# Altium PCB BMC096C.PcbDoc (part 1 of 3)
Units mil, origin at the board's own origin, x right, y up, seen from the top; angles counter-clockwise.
Board outline 5500 x 3200 mil, 4 copper layers (Top Layer, Signal Layer 1, Signal Layer 2, Bottom Layer), stack 61.6 mil thick; 174 components, 74 nets, 402 pads, 1110 vias.
Unrouted connection lines stored in the file: 741.
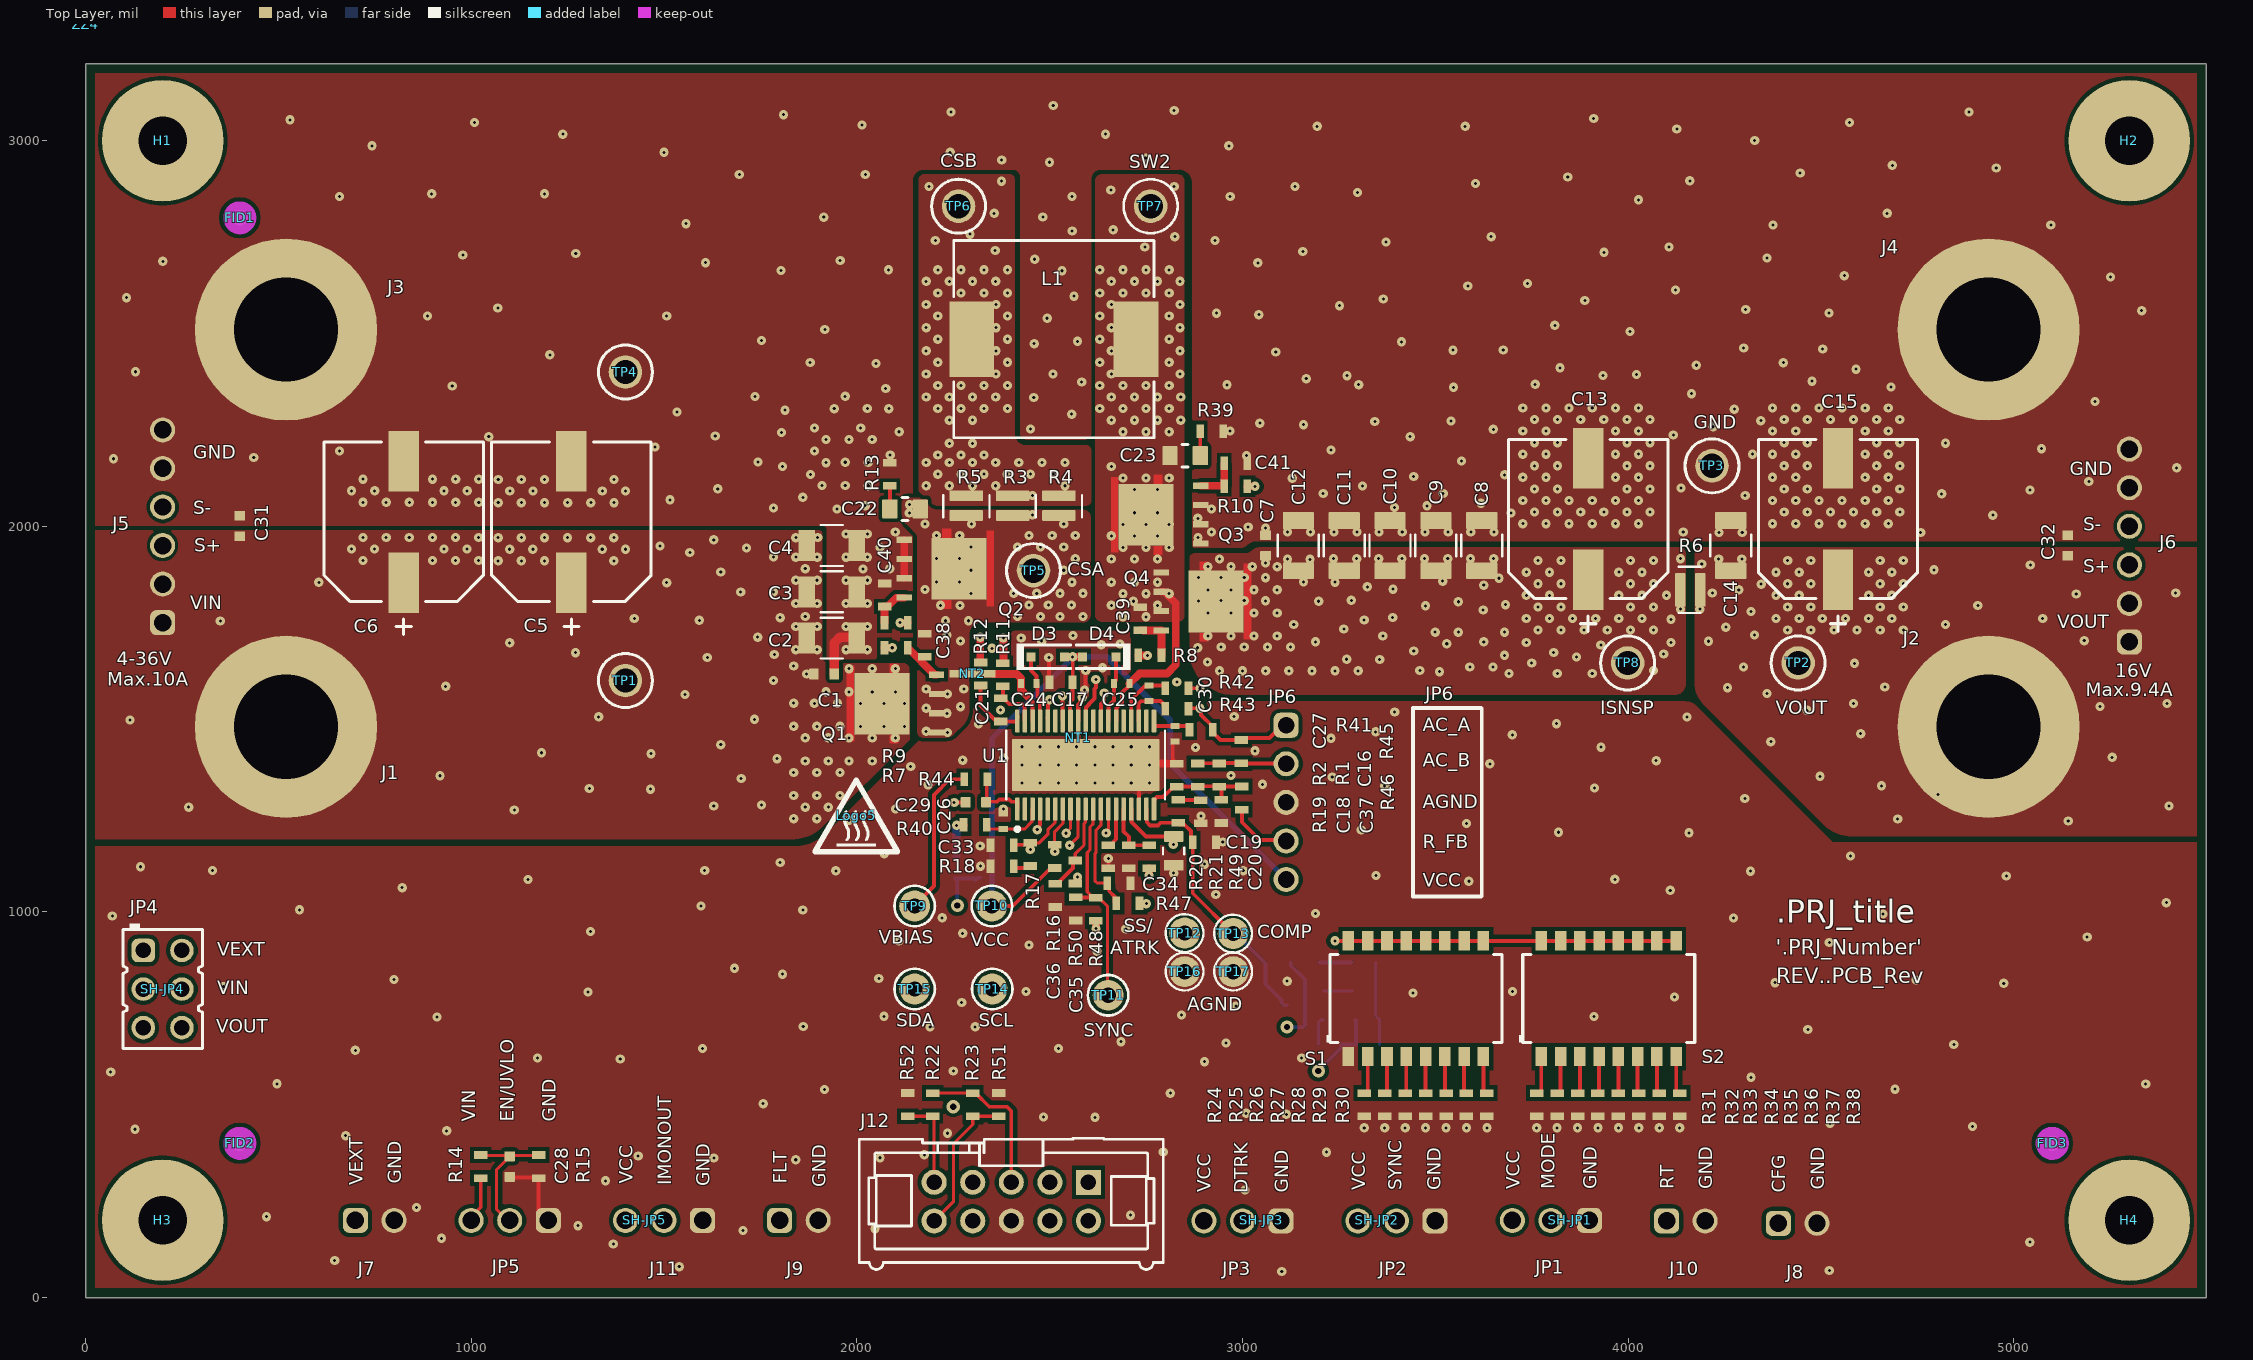
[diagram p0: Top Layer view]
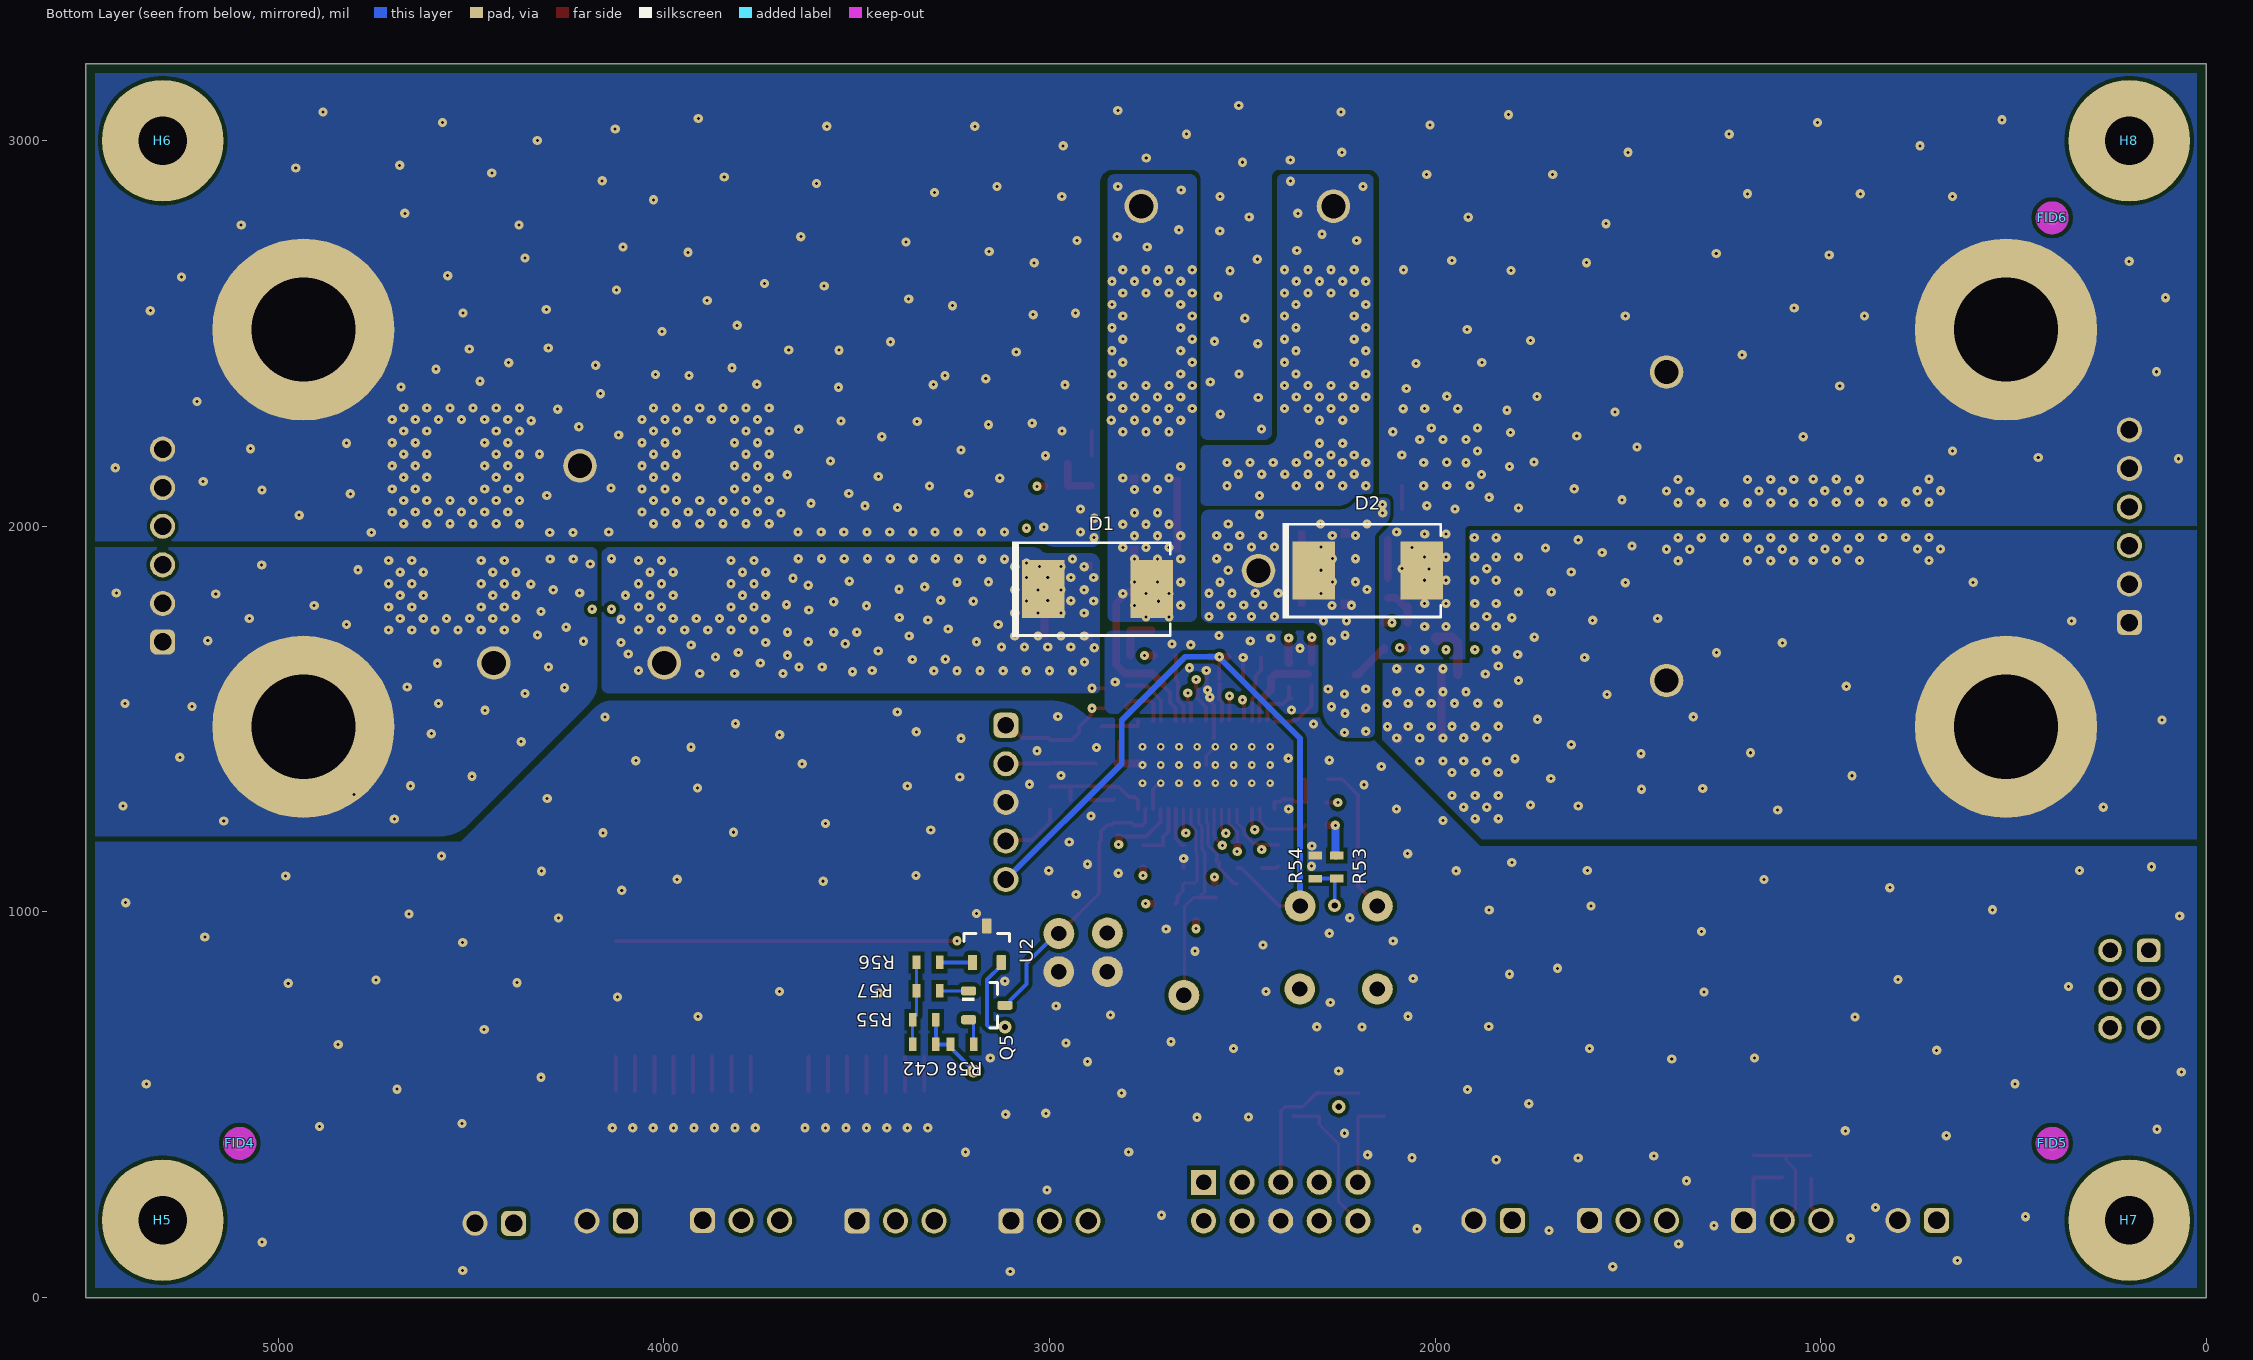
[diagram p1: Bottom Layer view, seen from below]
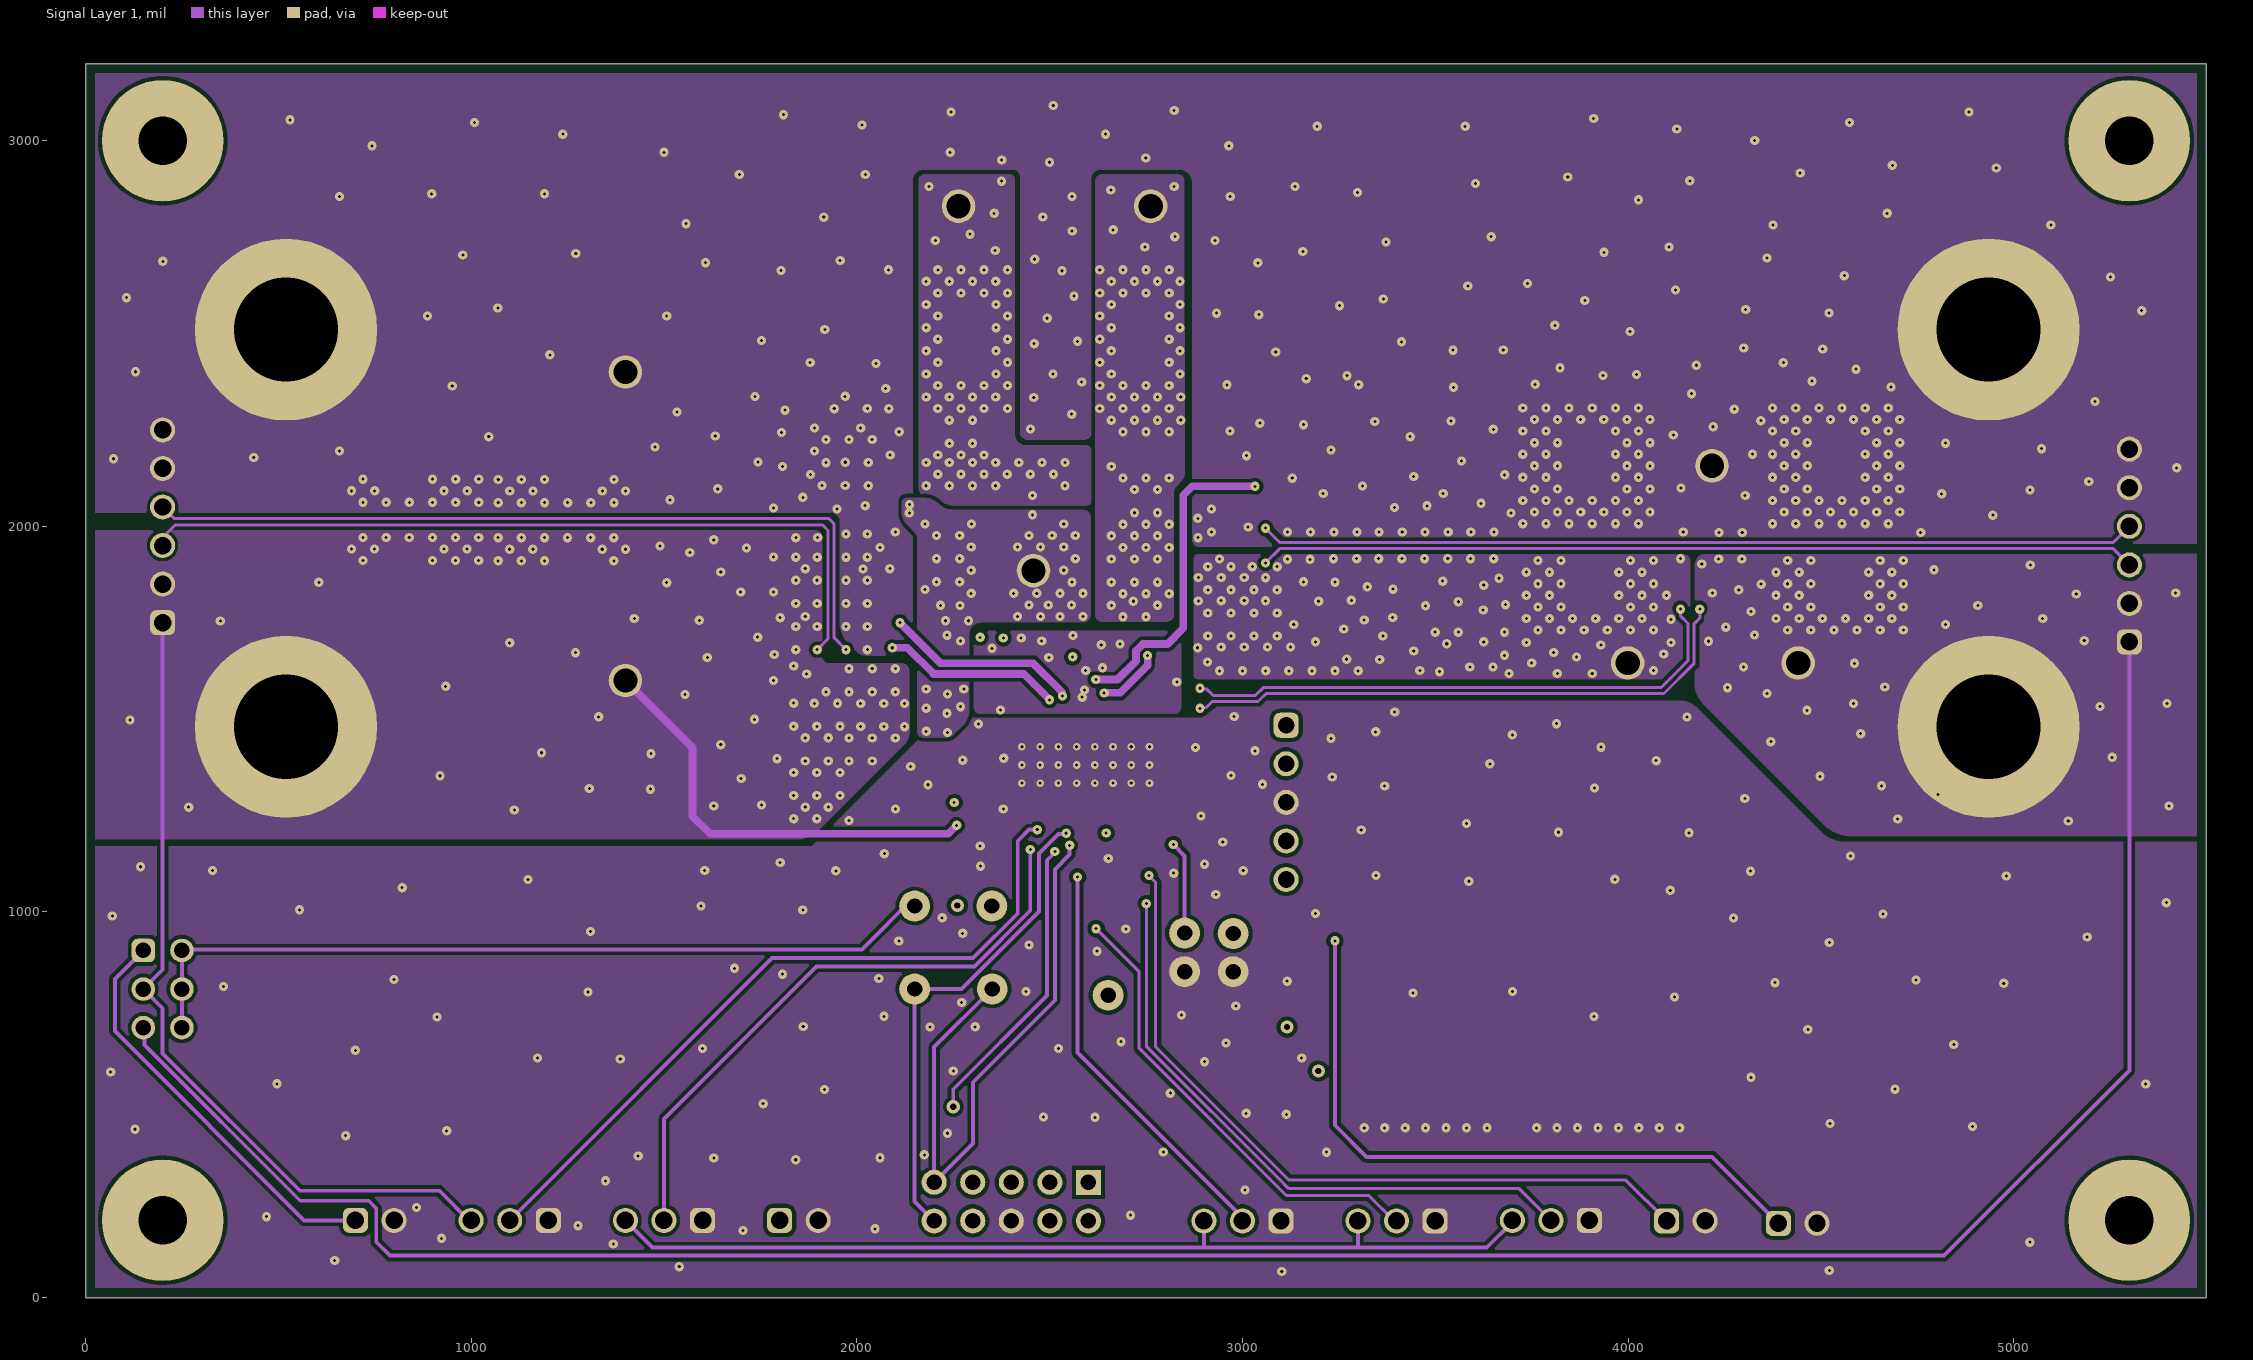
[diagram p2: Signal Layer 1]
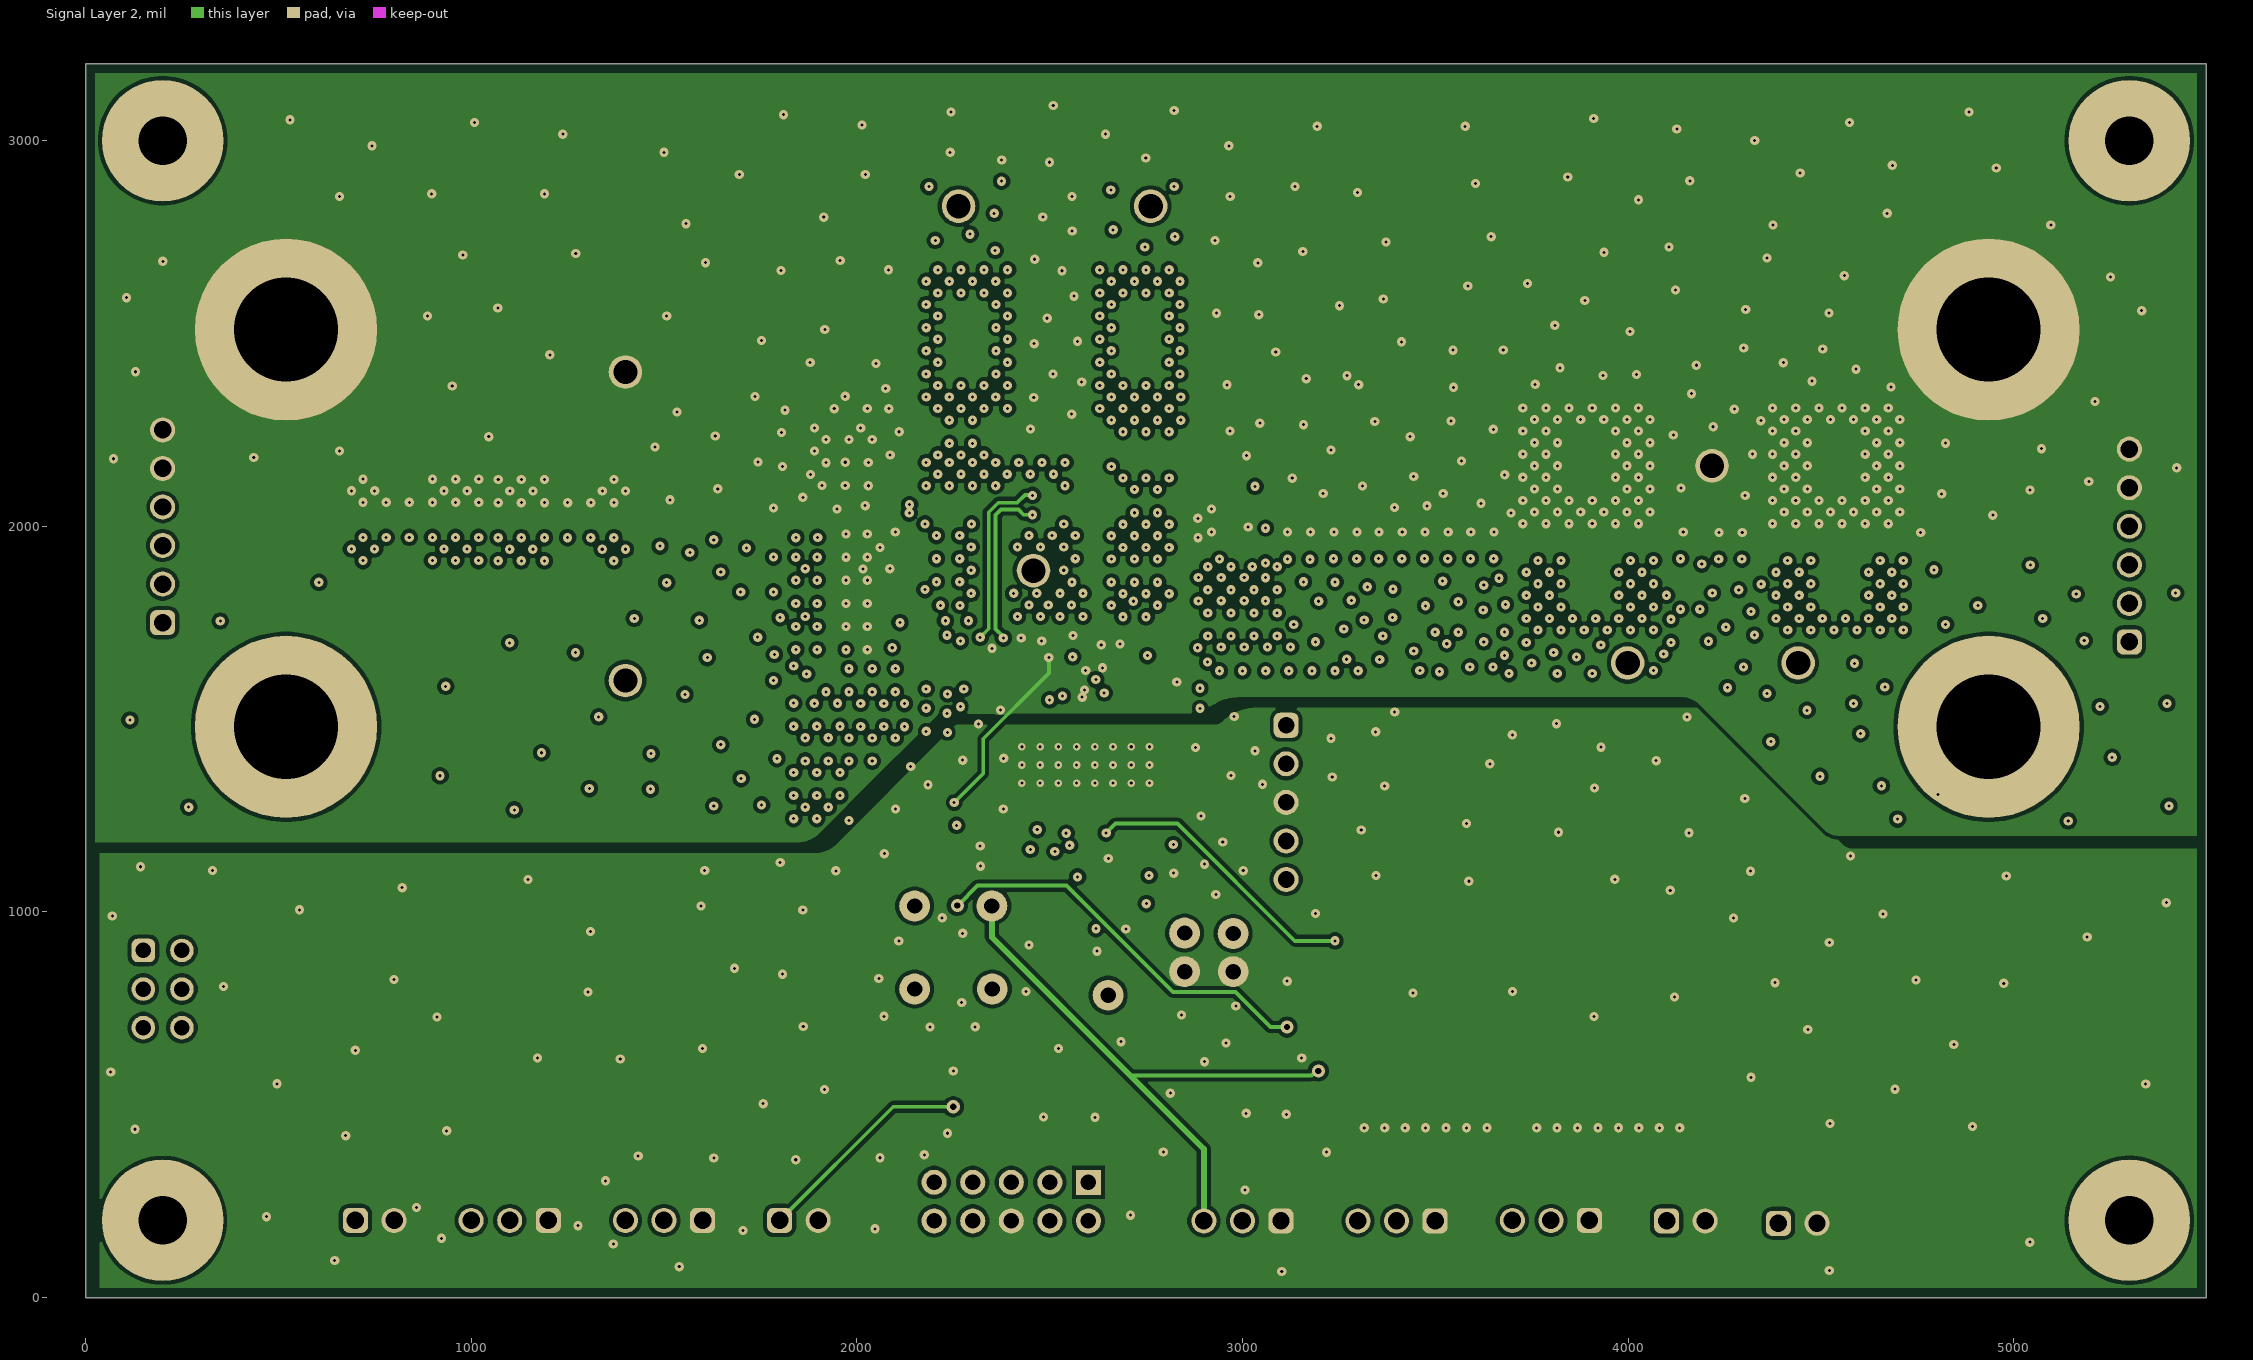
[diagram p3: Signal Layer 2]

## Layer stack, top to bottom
Top Solder: solder mask 0.4, Solder Resist, Dk 3.5
Top Layer: signal copper 2.8
Dielectric 1: prepreg 8, FR-4 High Tg, Dk 4.2
Signal Layer 1: signal copper 1.4
Dielectric 2: core 37.2, FR-4 High Tg, Dk 4.2
Signal Layer 2: signal copper 1.4
Dielectric 3: prepreg 8, FR-4 High Tg, Dk 4.2
Bottom Layer: signal copper 2.8
Bottom Solder: solder mask 0.4, Solder Resist, Dk 3.5

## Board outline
0,0 0,3200 5500,3200 5500,0

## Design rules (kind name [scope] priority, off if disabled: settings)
AcuteAngle [All] p1: minimum=4.50000000000000E+0001 checktracksonly=TRUE
AssemblyTestPointUsage [All] p1: valid=2
BoardOutlineClearance BoardOutlineClearance_MountingHoles [OnCopper and InComponentClass('Mounting Holes')] p1: gap=39.37 ignorepadtopadclearanceinfootprint=FALSE
BoardOutlineClearance BoardOutlineClearance_Poly [OnCopper and IsPoly] p2: gap=25 ignorepadtopadclearanceinfootprint=FALSE
BoardOutlineClearance [OnCopper and Not InComponentClass('Logo') and not InComponentClass('FiducialMark') and not InRegion(1000,500,4000,800) and not InPoly] p3: gap=40 ignorepadtopadclearanceinfootprint=FALSE
Clearance Clearance_Keepouts [((IsTrack Or IsArc) And Not InPoly) And IsFree and IsKeepOut vs ((IsTrack Or IsArc) And Not InPoly) And IsFree and IsKeepOut] p1: gap=0 ignorepadtopadclearanceinfootprint=FALSE
Clearance Clearance_Poly [InPolygon] p2: gap=10 ignorepadtopadclearanceinfootprint=TRUE
Clearance Clearance_FiducialMark [IsKeepOut and InComponentClass('FiducialMark') vs IsPad and InComponentClass('FiducialMark')] p3: gap=0 ignorepadtopadclearanceinfootprint=FALSE
Clearance [All] p4: gap=7.87 ignorepadtopadclearanceinfootprint=TRUE
ComponentClearance ComponentClearance_L1_TP [InComponent('L1')] p1: gap=25 collisioncheckmode=3 verticalgap=10 showdistances=FALSE
ComponentClearance ComponentClearance_TP [InComponent('TP15')or InComponent('TP16')or InComponent('TP17')or InComponent('TP18')or InComponent('TP23')or InComponent('TP24')or InComponent('TP12')or InComponent('TP13')or InComponent('TP21')or InComponent('TP22')] p2: gap=0 collisioncheckmode=3 verticalgap=0 showdistances=FALSE
ComponentClearance ComponentClearance_NT1 [InComponent('NT1') or InComponent('NT2')] p3: gap=0 collisioncheckmode=3 verticalgap=0 showdistances=FALSE
ComponentClearance ComponentClearance_MountingHoles_FiducialMarks [InComponentClass('Mounting Holes') vs InComponentClass('FiducialMark')] p4: gap=50 collisioncheckmode=3 verticalgap=10 showdistances=FALSE
ComponentClearance ComponentClearance_Shunt [InComponentClass('Header') vs InComponent('SH-JP1') or InComponent('SH-JP2') or InComponent('SH-JP3') or InComponent('SH-JP4') or InComponent('SH-JP5')] p5: gap=0 collisioncheckmode=3 verticalgap=0 showdistances=FALSE
ComponentClearance ComponentClearance_Logo [InComponentClass('Logo')] p6: gap=30 collisioncheckmode=3 verticalgap=10 showdistances=FALSE
ComponentClearance ComponentClearance_ScrewToNut [(HasFootprint('NY PMS 440 0025 PH')) vs (HasFootprint('Keystone_1902C'))] p7: gap=5 collisioncheckmode=3 verticalgap=10 showdistances=FALSE
ComponentClearance ComponentClearance_MountingHoles [InComponentClass('Mounting Holes')] p8: gap=100 collisioncheckmode=3 verticalgap=100000 showdistances=FALSE
ComponentClearance ComponentClearance_SmallPassives [HasFootprint('0201*') or HasFootprint('0402*') or HasFootprint('0508') or HasFootprint('0603*') or HasFootprint('0612') or HasFootprint('0805*') or HasFootprint('0815*') or HasFootprint('0830*') or HasFootprint('1206*') or HasFootprint('1210*') or HasFootprint('1808*') or HasFootprint('1812*') or HasFootprint('1825*') or HasFootprint('2010*') or HasFootprint('2220*') or HasFootprint('2225*') or HasFootprint('2512*') or HasFootprint('2728*') or HasFootprint('3518*') vs HasFootprint('0201*') or HasFootprint('0402*') or HasFootprint('0508') or HasFootprint('0603*') or HasFootprint('0612') or HasFootprint('0805*') or HasFootprint('0815*') or HasFootprint('0830*') or HasFootprint('1206*') or HasFootprint('1210*') or HasFootprint('1808*') or HasFootprint('1812*') or HasFootprint('1825*') or HasFootprint('2010*') or HasFootprint('2220*') or HasFootprint('2225*') or HasFootprint('2512*') or HasFootprint('2728*') or HasFootprint('3518*')] p9: gap=14.96 collisioncheckmode=3 verticalgap=10 showdistances=FALSE
ComponentClearance ComponentClearance_THtoSMT [IsThruComponent vs IsSMTComponent] p10: gap=30 collisioncheckmode=3 verticalgap=30 showdistances=FALSE
ComponentClearance ComponentClearance_THtoTH [IsThruComponent vs IsThruComponent] p11: gap=20 collisioncheckmode=3 verticalgap=30 showdistances=FALSE
ComponentClearance [All] p12: gap=20 collisioncheckmode=3 verticalgap=10 showdistances=FALSE
DiffPairsRouting [All] p1: maxlimit=100 minlimit=10 mostfreqgap=10 toplayer_minwidth=15 toplayer_maxwidth=15 toplayer_prefwidth=15 midlayer1_minwidth=15 midlayer1_maxwidth=15 midlayer1_prefwidth=15 midlayer2_minwidth=15 midlayer2_maxwidth=15 midlayer2_prefwidth=15 bottomlayer_minwidth=15 bottomlayer_maxwidth=15 bottomlayer_prefwidth=15 maxuncoupledlength=1000
FabricationTestPointUsage TestPointUsage [All] p1: valid=2 allowmultiple=FALSE
FabricationTestpoint Testpoint [All] p1: side=3 testpointundercomponent=TRUE minsize=40 maxsize=100 preferedsize=60 minholesize=0 maxholesize=40 preferedholesize=32 testpointgrid=1 allowsidetop=TRUE allowsidebottom=TRUE usegrid=TRUE gridtolerance=0.01
FanoutControl Fanout_LCC [IsLCC] p1: bgadir=Out bgaviamode=Centered fanoutstyle=Auto fanoutdirection=Alternating viagrid=1 // Fanout_LCC (Default Rule)
FanoutControl Fanout_BGA [IsBGA] p2: bgadir=Out bgaviamode=Centered fanoutstyle=Auto fanoutdirection=Alternating viagrid=1 // Fanout_BGA (Default Rule)
FanoutControl Fanout_Default [All] p4: bgadir=Out bgaviamode=Centered fanoutstyle=Auto fanoutdirection=Alternating viagrid=1 // Fanout_Default (Default Rule)
FanoutControl Fanout_Small [(CompPinCount < 5)] p5: bgadir=Out bgaviamode=Centered fanoutstyle=Auto fanoutdirection=OutThenIn viagrid=1 // Fanout_Small (Default Rule)
HoleSize [All] p1: absolutevalues=TRUE maxlimit=275 minlimit=7.87 maxpercent=80.000 minpercent=20.000
MinimumAnnularRing MinimumAnnularRing_ThermalPadVias [IsVia and InAnyComponent] p1: minimumring=5.91
MinimumAnnularRing [All] p2: minimumring=7.87
MinimumSolderMaskSliver MinimumSolderMaskSliver_Logo [InComponentClass('Logo') vs InComponentClass('Logo')] p1: minsoldermaskwidth=0.7
MinimumSolderMaskSliver [All] p2: minsoldermaskwidth=3.94
PlaneConnect [All] p1: planeconnectstyle=Relief reliefexpansion=10 reliefentries=4 reliefconductorwidth=10 reliefairgap=10
PolygonConnect [All] p1: connectstyle=Direct reliefconductorwidth=10 reliefentries=4 polygonreliefangle="90 Angle" airgapwidth=10
RoutingVias ThermalPadVias [IsVia and InAnyComponent] p1: holewidth=7.87 width=19.68 viastyle="Through Hole" minholewidth=7.87 minwidth=19.68 maxholewidth=12.99 maxwidth=23.62
RoutingVias [All] p2: holewidth=16 width=34 viastyle="Through Hole" minholewidth=7.87 minwidth=24 maxholewidth=40 maxwidth=65
SilkToBoardRegionClearance [Not ((IsComment or IsDesignator) And (Hide <> 'False')) and not InRegion(1000,500,4000,800)] p1:
SilkToSilkClearance SilkToSilkClearance_Pb-FreeLogo [(HasFootprint('Pb-Free_Overlay_Medium') OR HasFootprint('Pb-Free_Overlay_Small')) vs (HasFootprint('Pb-Free_Overlay_Medium') OR HasFootprint('Pb-Free_Overlay_Small'))] p1: silktosilkclearance=0
SilkToSilkClearance [All] p2: silktosilkclearance=3.94
SilkToSolderMaskClearance SilkToComponentPadClearance [(IsPad or IsFill or IsRegion) and InAnycomponent] p1: minsilkscreentomaskgap=5 clearancetoexposedcopper=TRUE
SilkToSolderMaskClearance "Silk to Solder Mask Opening" [All] p2: minsilkscreentomaskgap=3.94 clearancetoexposedcopper=FALSE
SolderMaskExpansion [All] p1: expansion=1.97 istentingtop=FALSE
UnRoutedNet [All] p1: checkbadconnections=TRUE
Width [All] p1: maxlimit=100 minlimit=6 preferedwidth=10
14 further rules are at their usual default settings.

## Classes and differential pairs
component class Header: J5 J6 J7 J8 J9 J10 J11 JP1 JP2 JP3 JP4 JP5 JP6
component class BMC096C: C1 C2 C3 C4 C5 C6 C7 C8 C9 C10 C11 C12 C13 C14 C15 C16 C17 C18 C19 C20 C21 C22 C23 C24 C25 C26 C27 C28 C29 C30 C31 C32 C33 C34 C35 C36 C37 C38 C39 C40 C41 C42 D1 D2 D3 D4 J1 J2 J3 J4 J5 J6 J7 J8 J9 J10 J11 J12 JP1 JP2 JP3 JP4 JP5 JP6 L1 NT1 NT2 Q1 Q2 Q3 Q4 Q5 R1 R2 R3 R4 R5 R6 R7 R8 R9 R10 R11 R12 R13 R14 R15 R16 R17 R18 R19 R20 R21 R22 R23 R24 R25 R26 R27 R28 R29 R30 R31 R32 R33 R34 R35 R36 R37 R38 R39 R40 R41 R42 R43 R44 R45 R46 R47 R48 R49 R50 R51 R52 R53 R54 R55 R56 R57 R58 S1 S2 TP1 TP2 TP3 TP4 TP5 TP6 TP7 TP8 TP9 TP10 TP11 TP12 TP13 TP14 TP15 TP16 TP17 U1 U2
component class "Mounting Holes": H1 H2 H3 H4
component class BMC096C_Hardware: FID1 FID2 FID3 FID4 FID5 FID6 H1 H2 H3 H4 H5 H6 H7 H8 Logo5 SH-JP1 SH-JP2 SH-JP3 SH-JP4 SH-JP5 ZZ2 ZZ3 ZZ4
component class FiducialMark: FID1 FID2 FID3 FID4 FID5 FID6
component class AssemblyNote: ZZ2 ZZ3 ZZ4

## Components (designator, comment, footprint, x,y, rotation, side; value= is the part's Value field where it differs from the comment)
C1 "GCM188L81H104KA57D" FP-GCM188L81H104KA57D_0603-MFG 1915,1616.93 r0 top
C2 "GCM32EC71H106KA03L" FP-GCM32EC71H106KA03L_1210-MFG 1935,1710 r180 top value=10µF
C3 "GCM32EC71H106KA03L" FP-GCM32EC71H106KA03L_1210-MFG 1935,1830 r180 top value=10µF
C4 "GCM32EC71H106KA03L" FP-GCM32EC71H106KA03L_1210-MFG 1935,1950 r180 top value=10µF
C5 "PCR1J101MCL1GS" CR_1000x1270 1260,2011.27 r90 top value=100uF
C6 "PCR1J101MCL1GS" CR_1000x1270 825,2011.27 r90 top value=100uF
C7 "GCM188L81H104KA57D" FP-GCM188L81H104KA57D_0603-MFG 3060,1950 r90 top
C8 "GCM32EC71H106KA03L" FP-GCM32EC71H106KA03L_1210-MFG 3620.57,1950 r270 top value=10µF
C9 "GCM32EC71H106KA03L" FP-GCM32EC71H106KA03L_1210-MFG 3501.57,1950 r270 top value=10µF
C10 "GCM32EC71H106KA03L" FP-GCM32EC71H106KA03L_1210-MFG 3382.57,1950 r270 top value=10µF
C11 "GCM32EC71H106KA03L" FP-GCM32EC71H106KA03L_1210-MFG 3264,1950 r270 top value=10µF
C12 "GCM32EC71H106KA03L" FP-GCM32EC71H106KA03L_1210-MFG 3145,1950 r270 top value=10µF
C13 "PCR1J101MCL1GS" CR_1000x1270 3896.71,2018.9 r90 top value=100uF
C14 "GCM32EC71H106KA03L" FP-GCM32EC71H106KA03L_1210-MFG 4266.29,1950 r270 top value=10µF
C15 "PCR1J101MCL1GS" CR_1000x1270 4544.43,2018.9 r90 top value=100uF
C16 "GRM1885C2A200JA01D" 0603S 2940.36,1354.65 r270 top value=20pF
C17 "GRM188R60J476ME15D" 0603S 2529.57,1596.16 r0 top value=47uF
C18 "CGA3E3X7R1H224K080AB" 0603S 2892.5,1259.7 r270 top value=0.22uF
C19 "06031C222JAT2A" 0603S 2901.25,1181.04 r0 top value=2200pF
C20 "GCM21B5C1H183JA16L" FP-GCM21B5C1H183JA16L_0805-MFG 2821.83,1158.17 r90 top value=18nF
C21 "GCM1885C1H101JA16J" 0603S 2373,1523.84 r90 top value=100pF
C22 "GRM2165C1H681JA01D" 0805_HV1 2125.06,2045.08 r0 top value=680pF
C23 "GRM2165C1H681JA01D" 0805_HV1 2851.36,2183 r180 top value=680pF
C24 "0402BB104KW500" 0402S 2445.98,1592 r0 top value=0.1uF
C25 "0402BB104KW500" 0402S 2687.04,1592 r180 top value=0.1uF
C26 "0402BB104KW500" 0402S 2380,1235 r270 top value=0.1uF
C27 "0402BB104KW500" 0402S 2824.91,1461.75 r270 top value=0.1uF
C28 "GCM188L81H104KA57D" FP-GCM188L81H104KA57D_0603-MFG 1100,339.5 r270 top
C29 "GCM188L81H104KA57D" FP-GCM188L81H104KA57D_0603-MFG 2308.95,1284.59 r0 top
C30 "0402BB104KW500" 0402S 2758,1567 r90 top value=0.1uF
C31 "GCM188L81H104KA57D" FP-GCM188L81H104KA57D_0603-MFG 400,2000.81 r90 top
C32 "GCM188L81H104KA57D" FP-GCM188L81H104KA57D_0603-MFG 5140,1950 r90 top
C33 "06031C222JAT2A" 0603S 2376.93,1173 r0 top value=2200pF
C34 "06031C102JAT2A" 0603S 2679.54,1074.91 r0 top value=1000pF
C35 "06031C102JAT2A" 0603S 2567.43,1007.87 r270 top value=1000pF
C36 "06031C102JAT2A" 0603S 2514.08,1042.87 r270 top value=1000pF
C37 "GRM1885C1H151JA01D" 0603S 2945.63,1260.58 r270 top value=150pF
C38 "GRM188R72A103KA01D" 0603S 2176.39,1691.59 r90 top value=0.01uF
C39 "GRM188R72A103KA01D" 0603S 2735.67,1760.07 r270 top value=0.01uF
C40 "GRM188R72A103KA01D" 0603S 2072,1821.71 r270 top value=0.01uF
C41 "GRM188R72A103KA01D" 0603S 2982.82,2163.32 r180 top value=0.01uF
C42 "C0603C183K1RACTU" 0603S 3325,656.26 r0 bottom value=0.018uF
D1 "B560C-13-F" SMC 2875.84,1836.98 r180 bottom value=60V
D2 "B560C-13-F" SMC 2175,1884.92 r180 bottom value=60V
D3 "PMEG6010CEJ,115" SOD-323F 2495,1661.5 r0 top value=60V
D4 "PMEG6010CEJ,115" SOD-323F 2629,1661.5 r180 top value=60V
FID1 "Fiducial" Fiducial10-20 400,2800 r0 top
FID2 "Fiducial" Fiducial10-20 400,400 r0 top
FID3 "Fiducial" Fiducial10-20 5100,400 r0 top
FID4 "Fiducial" Fiducial10-20 5100,400 r180 bottom
FID5 "Fiducial" Fiducial10-20 400,400 r180 bottom
FID6 "Fiducial" Fiducial10-20 400,2800 r180 bottom
H1 "NY PMS 440 0025 PH" "NY PMS 440 0025 PH" 200,3000 r0 top
H2 "NY PMS 440 0025 PH" "NY PMS 440 0025 PH" 5300,3000 r0 top
H3 "NY PMS 440 0025 PH" "NY PMS 440 0025 PH" 200,200 r0 top locked
H4 "NY PMS 440 0025 PH" "NY PMS 440 0025 PH" 5300,200 r0 top
H5 "1902C" Keystone_1902C 5300,200 r180 bottom locked
H6 "1902C" Keystone_1902C 5300,3000 r180 bottom
H7 "1902C" Keystone_1902C 200,200 r180 bottom locked
H8 "1902C" Keystone_1902C 200,3000 r180 bottom locked
J1 "108-0740-001" Johnson_108-0740-001 520,1480 r0 top
J2 "108-0740-001" Johnson_108-0740-001 4935,1480 r0 top
J3 "108-0740-001" Johnson_108-0740-001 520,2510 r0 top
J4 "108-0740-001" Johnson_108-0740-001 4935,2510 r0 top
J5 "61300611121" WURTH_61300611121 200,2000 r90 top
J6 "61300611121" WURTH_61300611121 5300,1950 r90 top
J7 "61300211121" WURTH_61300211121 750,200 r0 top
J8 "61300211121" WURTH_61300211121 4440,192.46 r0 top
J9 "61300211121" WURTH_61300211121 1850,200 r0 top
J10 "61300211121" WURTH_61300211121 4150,198.77 r0 top
J11 "61300311121" WURTH_61300311121 1500,200 r180 top
J12 "N2510-6002-RB" CONN_2510-6002 2400.67,248.77 r180 top
JP1 "61300311121" WURTH_61300311121 3800,200 r180 top
JP2 "61300311121" WURTH_61300311121 3399.6,198.77 r180 top
JP3 "61300311121" WURTH_61300311121 3000.04,198.77 r180 top
JP4 "HTSW-103-07-G-D" Samtec_HTSW-103-07-x-D 200,800 r0 top
JP5 "61300311121" WURTH_61300311121 1100,200 r180 top
JP6 "61300511121" Wurth_61300511121 3113.44,1284.08 r270 top
L1 "IHLP5050FDER1R8M01" IHLP-5050FD 2511.06,2485.11 r0 top value=1.8uH
Logo5 "CAUTION HOT SURFACE" IEC_HotSurface_Small 1998.65,1249.35 r0 top
NT1 "Net-Tie" Net-Tie_10mil 2574,1452 r270 top net-tie
NT2 "Net-Tie" Net-Tie_20milWide_60milLong 2299.97,1617.37 r180 top net-tie
Q1 "SQJ422EP-T1-GE3" PowerPAK_SO-8L 2096.69,1540 r180 top value=40V
Q2 "SQJ422EP-T1-GE3" PowerPAK_SO-8L 2233.31,1890 r0 top value=40V
Q3 "SQJ422EP-T1-GE3" PowerPAK_SO-8L 2781.69,2030 r180 top value=40V
Q4 "SQJ422EP-T1-GE3" PowerPAK_SO-8L 2900,1805 r0 top value=40V
Q5 "BC807-40LT1G" SOT-23 3162.89,757.78 r180 bottom value="45 V"
R1 "RC0603FR-0771K5L" 0603S 2883.75,1354.65 r270 top value=71.5k
R2 "RC0603FR-074K7L" 0603S 2830.06,1354.2 r270 top value=4.70k
R3 "KRL2012E-M-R004-F-T5" FP-KRL2012E-M-R004-F-T5_2012-MFG 2404.24,2053.56 r90 top value=4m
R4 "KRL2012E-M-R004-F-T5" FP-KRL2012E-M-R004-F-T5_2012-MFG 2524.24,2053.56 r90 top value=4m
R5 "KRL2012E-M-R004-F-T5" FP-KRL2012E-M-R004-F-T5_2012-MFG 2284.24,2053.56 r90 top value=4m
R6 "KRL2012E-M-R004-F-T5" FP-KRL2012E-M-R004-F-T5_2012-MFG 4161.29,1835 r0 top value=4m
R7 "CRCW06033R00JNEA" 0603S 2102,1685 r0 top value=3.0
R8 "CRCW06033R00JNEA" 0603S 2760,1665 r0 top value=3.0
R9 "CRCW06033R00JNEA" 0603S 2102,1750 r0 top value=3.0
R10 "CRCW06033R00JNEA" 0603S 2982.74,2103.47 r0 top value=3.0
R11 "CRCW0603100RFKEAHP" 0603S 2378,1615 r90 top value=100
R12 "CRCW0603100RFKEAHP" 0603S 2321,1617 r90 top value=100
R13 "CRCW06033R00JNEA" 0603S 2085.69,2135.11 r270 top value=3.0
R14 "RC0603FR-0775KL" 0603S 1025,339.5 r270 top value=75.0k
R15 "RC0603FR-0739KL" 0603S 1175,339.5 r90 top value=39.0k
R16 "RT0603BRD0710KL" 0603S 2513,1144 r90 top value=10.0k
R17 "RC0603FR-0782KL" 0603S 2450,1149 r90 top value=82.0k
R18 "RMCF0603ZT0R00" 0603S 2376.73,1118.57 r0 top value=0
R19 "RC0603FR-072KL" 0603S 2833.28,1261.17 r270 top value=2.00k
R20 "CRCW060368K1FKEA" 0603S 2652,1143 r90 top value=68.1k
R21 "RC0603FR-0778K7L" 0603S 2705,1143 r90 top value=78.7k
R22 "RC0603FR-072KL" 0603S 2197.33,500.06 r90 top value=2.00k
R23 "RC0603FR-072KL" 0603S 2300.67,500 r90 top value=2.00k
R24 "CRCW0603511RFKEA" 0603S 3316,500 r90 top value=511
R25 "CRCW06031K15FKEA" 0603S 3369,500 r90 top value=1.15k
R26 "RC0603FR-071K87L" 0603S 3422,500 r90 top value=1.87k
R27 "RC0603FR-072K7L" 0603S 3475,500 r90 top value=2.70k
R28 "CRCW06033K83FKEA" 0603S 3528,500 r90 top value=3.83k
R29 "RC0603FR-075K1L" 0603S 3581,500 r90 top value=5.10k
R30 "RC0603FR-076K49L" 0603S 3634,500 r90 top value=6.49k
R31 "RC0603FR-078K25L" 0603S 3763,500 r90 top value=8.25k
R32 "CRCW060310K5FKEA" 0603S 3816,500 r90 top value=10.5k
R33 "RC0603FR-0713K3L" 0603S 3869,500 r90 top value=13.3k
R34 "CRCW060316K2FKEA" 0603S 3922,500 r90 top value=16.2k
R35 "RC0603FR-0720K5L" 0603S 3975,500 r90 top value=20.5k
R36 "CRCW060324K9FKEA" 0603S 4028,500 r90 top value=24.9k
R37 "CRCW060330K1FKEA" 0603S 4081,500 r90 top value=30.1k
R38 "CRCW060335K7FKEA" 0603S 4134,500 r90 top value=35.7k
R39 "CRCW06033R00JNEA" 0603S 2920.67,2246.84 r180 top value=3.0
R40 "RMCF0603ZT0R00" 0603S 2307,1225.5 r180 top value=0
R41 "RMCF0603ZT0R00" 0603S 2893,1473 r0 top value=0
R42 "RMCF0603ZT0R00" 0603S 2830,1580 r0 top value=0
R43 "RMCF0603ZT0R00" 0603S 2830,1527 r0 top value=0
R44 "RMCF0603ZT0R00" 0603S 2308.78,1344.16 r180 top value=0
R45 "RC0603FR-0710RL" 0603S 2997.63,1415.53 r90 top value=10.0
R46 "RMCF0603ZT0R00" 0603S 2998.63,1295.19 r270 top value=0
R47 "RMCF0603ZT0R00" 0603S 2703.12,1021.91 r180 top value=0
R48 "RMCF0603ZT0R00" 0603S 2620.15,1006.91 r90 top value=0
R49 "RMCF0603ZT0R00" 0603S 2757.9,1143 r270 top value=0
R50 "RMCF0603ZT0R00" 0603S 2566.5,1103.4 r90 top value=0
R51 "RMCF0603ZT0R00" 0603S 2368.06,500.38 r270 top value=0
R52 "RMCF0603ZT0R00" 0603S 2132.32,500.12 r270 top value=0
R53 "RC0603FR-07100KL" 0603S 2255.15,1116.38 r90 bottom value=100k
R54 "RC0603FR-074K7L" 0603S 2311.23,1116.07 r270 bottom value=4.70k
R55 "CRCW060310K0FKEA" 0603S 3325,720 r180 bottom value=10.0k
R56 "RC0603FR-0710RL" 0603S 3315,869 r0 bottom value=10.0
R57 "CRCW060310K0FKEA" 0603S 3315,795.19 r0 bottom value=10.0k
R58 "RC0603FR-0710RL" 0603S 3226.87,656.26 r180 bottom value=10.0
S1 "218-8LPST" SW_218-8LP 3450,775 r90 top
S2 "218-8LPST" SW_218-8LP 3950,775 r90 top
SH-JP1 "M7582-05" Harwin_M7582-05 3850,200 r0 top
SH-JP2 "M7582-05" Harwin_M7582-05 3350,200 r0 top
SH-JP3 "M7582-05" Harwin_M7582-05 3050,200 r0 top
SH-JP4 "M7582-05" Harwin_M7582-05 200,800 r180 top
SH-JP5 "M7582-05" Harwin_M7582-05 1450,200 r180 top
TP1 "5010" Keystone5010 1400,1600 r180 top
TP2 "5013" Keystone5013 4441.12,1645.57 r180 top
TP3 "5011" Keystone5011 4217.79,2156.84 r180 top
TP4 "5011" Keystone5011 1400,2400 r180 top
TP5 "5012" Keystone5012 2458.3,1884.92 r0 top
TP6 "5012" Keystone5012 2264,2830 r0 top
TP7 "5128" Keystone5128 2762.06,2830 r0 top
TP8 "5013" Keystone5013 3999.02,1645.57 r0 top
TP9 "5004" Keystone5004 2150.08,1015.24 r90 top
TP10 "5004" Keystone5004 2350.33,1015.33 r90 top
TP11 "5004" Keystone5004 2651.77,783.88 r90 top
TP12 "5004" Keystone5004 2849.98,945.21 r90 top
TP13 "5004" Keystone5004 2975.84,943.95 r90 top
TP14 "5004" Keystone5004 2351.24,800 r90 top
TP15 "5004" Keystone5004 2150.08,800 r90 top
TP16 "5001" Keystone5001 2850,845.34 r90 top
TP17 "5001" Keystone5001 2976.08,845.34 r90 top
U1 "LM5177DCPR" DCP0038A-MFG 2593.62,1381 r90 top
U2 "TLVH432ACDBZR" DBZ0003A_N 3162.89,916 r90 bottom
ZZ2 "These assemblies are ESD sensitive, ESD precautions shall be observed." AssemblyNote 0,3500 r0 top
ZZ3 "These assemblies must be clean and free from flux and all contaminants. Use of no clean flux is not acceptable." AssemblyNote 0,3400 r0 top
ZZ4 "These assemblies must comply with workmanship standards IPC-A-610 Class 2, unless otherwise specified." AssemblyNote 0,3300 r0 top

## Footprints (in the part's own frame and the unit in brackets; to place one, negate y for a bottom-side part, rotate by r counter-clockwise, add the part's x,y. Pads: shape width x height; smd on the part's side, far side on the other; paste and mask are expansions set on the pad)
0402S [mil] "Based on C0402S footprint from PADS legacy"
  rect 15x24 smd: 1(-20,0) 2(20,0)
  body extent -22,-12 22,12, height 24
0603S [mil]
  rect 20x35 smd: 1(-30,0) 2(30,0)
  body extent -34,-19 34,19, height 39
0805_HV1 [mm] "Custom footprint based on analyzing multiple manufacturer recommendations"
  rrect10% 1x1.25 smd: 1(-1,0) 2(1,0)
  silkscreen extent -0.2,-0.75 0.2,0.75, body extent -1.1,-0.72 1.1,0.73, height 1.45
AssemblyNote [mil] "Assembly Note"
CONN_2510-6002 [mm] "3M 2500 series TS-0770-L December 15, 2011"
  rect 1.65x1.65 hole 1.016 mask+0: 1(-5.08,-1.27)
  round 1.65 hole 1.016 mask+0: 2(-5.08,1.27) 3(-2.54,-1.27) 4(-2.54,1.27) 5(0,-1.27) 6(0,1.27) 7(2.54,-1.27) 8(2.54,1.27) 9(5.08,-1.27) 10(5.08,1.27)
  silkscreen extent -10.01,-4.17 10.01,4.47, body extent -10.01,-4.11 10.01,4.52, height 9.92
CR_1000x1270 [mm] "SMD, 2-Leads, Dia 10.5mm, Pin Spacing 8mm"
  rect 4x2 smd: 1(-4,0) 2(4,0)
  silkscreen extent -7.4,-5.25 5.25,5.25, body extent -5.25,-5.25 5.25,5.25, height 12.71
DBZ0003A_N [mm] "SOT23, 3-Leads, Body 2.9x1.3mm, Pitch 0.95mm, Lead Span 2.4mm, IPC Medium Density"
  rrect17% 1x0.6 smd: 1(-1.2,0.95) 2(-1.2,-0.95) 3(1.2,0)
  silkscreen extent 0.2,-1.5 0.7,1.5, body extent -1.26,-1.46 1.26,1.46, height 0.98
DCP0038A-MFG [mm]
  rrect33% 1.5x0.3 smd paste+0 mask+0: 1(-2.9,4.5) 2(-2.9,4) 3(-2.9,3.5) 4(-2.9,3) 5(-2.9,2.5) 6(-2.9,2) 7(-2.9,1.5) 8(-2.9,1) 9(-2.9,0.5) 10(-2.9,0) 11(-2.9,-0.5) 12(-2.9,-1) 13(-2.9,-1.5) 14(-2.9,-2) 15(-2.9,-2.5) 16(-2.9,-3) 17(-2.9,-3.5) 18(-2.9,-4) 19(-2.9,-4.5) 20(2.9,-4.5) 21(2.9,-4) 22(2.9,-3.5) 23(2.9,-3) 24(2.9,-2.5) 25(2.9,-2) 26(2.9,-1.5) 27(2.9,-1) 28(2.9,-0.5) 29(2.9,0) 30(2.9,0.5) 31(2.9,1) 32(2.9,1.5) 33(2.9,2) 34(2.9,2.5) 35(2.9,3) 36(2.9,3.5) 37(2.9,4) 38(2.9,4.5)
  rrect3% 3.4x9.7 smd paste-1000 mask-1000: 39(0,0)
  silkscreen extent -4.35,-5.23 2.25,5.23, body extent -3.75,-5.15 3.75,5.15, height 0.25
Fiducial10-20 [mm]
  round 1 smd mask+0.5: 1(0,0)
  Top Layer keep-out circle w1.178: c0,0 r0.5
FP-GCM21B5C1H183JA16L_0805-MFG [mm]
  rrect14% 0.7x1.3 smd paste+0 mask+0: 1(-0.95,0) 2(0.95,0)
  silkscreen extent -0.23,-0.7 0.23,0.7, body extent -1.4,-0.8 1.4,0.8, height 0.25
FP-GCM32EC71H106KA03L_1210-MFG [mm]
  rrect9% 1.1x2.05 smd paste+0 mask+0: 1(-1.65,0) 2(1.65,0)
  silkscreen extent -0.72,-1.35 0.72,1.35, body extent -2.3,-1.45 2.3,1.45, height 0.25
FP-GCM188L81H104KA57D_0603-MFG [mm]
  rrect15% 0.65x0.7 smd paste+0 mask+0: 1(-0.675,0) 2(0.675,0)
  body extent -1.1,-0.55 1.1,0.55, height 0.25
FP-KRL2012E-M-R004-F-T5_2012-MFG [mm]
  rrect14% 0.7x2.2 smd paste+0 mask+0: 1(-0.65,0) 2(0.65,0)
  silkscreen extent -0.77,-1.53 0.67,1.53, body extent -1.1,-1.2 1.1,1.2, height 0.25
Harwin_M7582-05 [mil] "Single Operation 2.54mm Pitch Open Top Jumper Socket"
  body extent -98,-47 98,47, height 236
IEC_HotSurface_Small [mil]
  silkscreen extent -107,-93 107,92
IHLP-5050FD [mm] "Vishay Dale recommended land pattern.  Document 34123 rev 18-Sep-09"
  rect 2.945x4.95 smd: 1(-5.407,0) 2(5.407,0)
  silkscreen extent -6.6,-6.5 6.6,6.5, body extent -6.86,-6.45 6.86,6.45, height 6.5
Johnson_108-0740-001 [mm] "Banana Jack Uninsulated Standard Type"
  round 12 hole 6.858: 1(0,0)
  body extent -4.77,-5.43 4.75,5.57, height 2.39
Keystone5001 [mil] "For Keystone 500x miniature loop terminals"
  round 80 hole 40: 1(0,0)
  silkscreen extent -49,-49 49,49, body extent -49,-49 49,49, height 182
Keystone5004 [mil] "For Keystone 500x miniature loop terminals"
  round 80 hole 40: 1(0,0)
  silkscreen extent -52,-52 52,52, body extent -49,-49 49,49, height 182
Keystone5010 [mil] "Keystone Multipurpose loops"
  round 87 hole 63: 1(0,0)
  silkscreen extent -70,-70 70,70, body extent -63,-63 63,62, height 319
Keystone5011 [mil] "Keystone Multipurpose loops"
  round 87 hole 63: 1(0,0)
  silkscreen extent -70,-70 70,70, body extent -63,-63 63,62, height 319
Keystone5012 [mil] "Keystone Multipurpose loops"
  round 87 hole 63: 1(0,0)
  silkscreen extent -70,-70 70,70, body extent -63,-63 63,62, height 319
Keystone5013 [mil] "Keystone Multipurpose loops"
  round 87 hole 63: 1(0,0)
  silkscreen extent -70,-70 70,70, body extent -63,-63 63,62, height 319
Keystone5128 [mil] "Keystone Multipurpose loops"
  round 87 hole 63: 1(0,0)
  silkscreen extent -70,-70 70,70, body extent -63,-63 63,62, height 319
Keystone_1902C [mil] "Hex Standoff, 4-40 threaded, nylon"
  round 1 on Mech4: 0(0,0)
  body extent -145,-126 146,126, height 501
Net-Tie_10mil [mil] "10mil net tie, no solder mask opening, no solder paste"
  rect 10x10 smd paste-5 mask-5: 1(-10,0) 2(10,0)
  Top Layer region: -6,5 6,5 6,-5 -6,-5
Net-Tie_20milWide_60milLong [mil] "20mil net tie, no solder mask opening, no solder paste"
  rect 60x20 smd paste-10 mask-10: 1(-30,0) 2(30,0)
"NY PMS 440 0025 PH" [mm] "4-40 nylon screw and mounting hole"
  round 8 hole 3.2: 1(0,0)
  body extent -3.3,-3.3 3.3,3.3, height 2.69
PowerPAK_SO-8L [mm] "based on Vishay recommended land pattern Document 63818 Feb 7, 2012"
  rect 1x0.41 smd: 1(-2.805,1.905) 2(-2.805,0.635) 3(-2.805,-0.635) 4(-2.805,-1.905)
  rect 3.63x4.061 smd: 5(0.805,0)
  Top Layer region: -0.298,-2.64 0.298,-2.64 0.298,-2.03 -0.298,-2.03
  Top Layer region: -0.298,2.03 0.298,2.03 0.298,2.64 -0.298,2.64
  Top Layer region: 2.615,-2.5 3.125,-2.5 3.125,2.5 2.615,2.5
  body extent -3.07,-2.57 3.08,2.57, height 1.21
Samtec_HTSW-103-07-x-D [mm] "Header, 2.54mm, 3x2, Gold, TH"
  rrect50% 1.55x1.55 hole 1.02: 1(-1.27,2.54)
  round 1.55 hole 1.02: 2(1.27,2.54) 3(-1.27,0) 4(1.27,0) 5(-1.27,-2.54) 6(1.27,-2.54)
  silkscreen extent -2.61,-3.91 2.61,4.3, body extent -2.51,-3.81 2.51,3.81, height 8.38
SMC [mil] "Molded Diode, 2-Leads, Body 6.9x5.8mm, IPC Medium Density, based on OnSemi component dimensions and land patterns"
  rect 110x150 smd: 1(-140.49,0) 2(140.49,0)
  silkscreen extent -221,-123 189,124, body extent -156,-116 156,116, height 91
SOD-323F [mm] "NXP recommended land pattern"
  rect 0.6x0.6 smd paste-0.05: 1(-1.1,0) 2(1.1,0)
  silkscreen extent -2.06,-0.86 1.53,0.86, body extent -1.35,-0.67 1.35,0.68, height 0.79
SOT-23 [mm] "SOT23, 3-Leads, Body 2.9x1.3mm, Pitch 0.95mm, Lead Span 2.5mm, IPC Medium Density"
  rrect50% 1x0.6 smd: 1(-1.2,0.95) 2(-1.2,-0.95) 3(1.2,0)
  silkscreen extent -1.63,-1.5 0.7,1.5, body extent -1.16,-1.45 1.21,1.45, height 1
SW_218-8LP [mm] "SMD, 16-Leads, Body 11.33x5.8mm, Pitch 1.27mm"
  rect 1.27x0.76 smd: 1(-3.81,4.445) 2(-3.81,3.175) 3(-3.81,1.905) 4(-3.81,0.635) 5(-3.81,-0.635) 6(-3.81,-1.905) 7(-3.81,-3.175) 8(-3.81,-4.445) 9(3.81,-4.445) 10(3.81,-3.175) 11(3.81,-1.905) 12(3.81,-0.635) 13(3.81,0.635) 14(3.81,1.905) 15(3.81,3.175) 16(3.81,4.445)
  silkscreen extent -2.9,-5.67 2.9,5.9, body extent -4.22,-5.66 4.22,5.66, height 2.62
WURTH_61300211121 [mm] "Header, 2.54mm, 2x1, TH"
  rrect50% 1.65x1.65 hole 1.15: 1(-1.27,0)
  round 1.65 hole 1.15: 2(1.27,0)
  body extent -2.54,-1.27 2.54,1.27, height 8.54
WURTH_61300311121 [mm] "Header, 2.54mm, 3x1, TH"
  rrect50% 1.65x1.65 hole 1.15: 1(-2.54,0)
  round 1.65 hole 1.15: 2(0,0) 3(2.54,0)
  body extent -3.81,-1.27 3.81,1.27, height 8.54
Wurth_61300511121 [mm] "Header, 2.54mm, 5x1, TH"
  rrect50% 1.65x1.65 hole 1.1: 1(-5.08,0)
  round 1.65 hole 1.1: 2(-2.54,0) 3(0,0) 4(2.54,0) 5(5.08,0)
  body extent -6.35,-1.27 6.35,1.27, height 8.54
WURTH_61300611121 [mm] "Header, 2.54mm, 6x1, TH"
  rrect50% 1.65x1.65 hole 1.15: 1(-6.35,0)
  round 1.65 hole 1.15: 2(-3.81,0) 3(-1.27,0) 4(1.27,0) 5(3.81,0) 6(6.35,0)
  body extent -7.62,-1.27 7.62,1.27, height 8.54

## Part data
C1 C7 C28 C29 C31 C32: library part CMP-0086535-1, "0.1µF ±10% 50V Ceramic Capacitor X8L 0603 (1608 Metric)", Manufacturer="Murata Electronics North America", TempCo=-40+15%, Tolerance_%=10%
C2 C3 C4 C8 C9 C10 C11 C12 C14: library part CMP-0092251-1, "Ceramic Capacitor for Automotive 10uF ±10% 50VDC X7S 1210 Embossed T/R", Manufacturer=Murata, Operating Temperature Range="-55°C to +125°C", TempCo=22%, Temperature Characteristic=X7S, Tolerance_%=10%, ValueDisplayed=10uF
C5 C6 C13 C15: library part CMP-0012274-3, "CAP, Aluminum Polymer, 100 uF, 63 V, +/- 20%, 0.024 ohm, SMD, 2-Leads, Dia 10.5mm, Pin Spacing 8mm SMD", Cap_Case=10x12.7mm, Manufacturer=Nichicon, Supplier Part Number 1=493-13783-1-ND, Tolerance_%=20%, Value1="0.024 ohm", Value2=63V, ValueDisplayed=100uF
C16: library part CMP-0007253-4, "CAP, CERM, 20 pF, 100 V, +/- 5%, C0G/NP0, 0603", Cap_Case=0603, Manufacturer=MuRata, Supplier Part Number 1=490-1334-1-ND, TempCo=C0G/NP0, Tolerance_%=5%, Value1=Unknown, Value2=100V, ValueDisplayed=20pF
C17: library part CMP-0007313-5, "CAP, CERM, 47 uF, 6.3 V, +/- 20%, X5R, 0603", Cap_Case=0603, Manufacturer=MuRata, TempCo=X5R, Tolerance_%=20%, Value1=Unknown, Value2=6.3V, ValueDisplayed=47uF
C18: library part CMP-0007094-5, "CAP, CERM, 0.22 uF, 50 V, +/- 10%, X7R, AEC-Q200 Grade 1, 0603", Cap_Case=0603, Manufacturer=TDK, Supplier Part Number 1=445-6926-1-ND, TempCo=X7R, Tolerance_%=10%, Value1="0.021699 ohm", Value2=50V, ValueDisplayed=0.22uF
C19 C33: library part CMP-0006736-4, "CAP, CERM, 2200 pF, 100 V, +/- 5%, X7R, 0603", Cap_Case=0603, Manufacturer=AVX, Supplier Part Number 1=478-3705-1-ND, TempCo=X7R, Tolerance_%=5%, Value1="0.192 ohm", Value2=100V, ValueDisplayed=2200pF
C20: library part CMP-0092440-1, "Ceramic Capacitor for Automotive 18nF ±5% 50VDC C0G 0805 Embossed T/R", Manufacturer=Murata, Operating Temperature Range="-55°C to +125°C", TempCo=30ppm/°C, Temperature Characteristic=C0G, Tolerance_%=5%, ValueDisplayed=18nF
C21: library part CMP-0750041-1, "CAP, CERM, 100 pF, 50 V,+/- 5%, C0G/NP0, AEC-Q200 Grade 1, 0603", Cap_Case=0603, Manufacturer=MuRata, TempCo=C0G/NP0, Tolerance_%=5%, Value2=50V, ValueDisplayed=100pF
C22 C23: library part CMP-0008089-2, "CAP, CERM, 680 pF, 50 V, +/- 5%, C0G/NP0, 0805", Cap_Case=0805, Manufacturer=MuRata, Supplier Part Number 1=490-1619-1-ND, TempCo=C0G/NP0, Tolerance_%=5%, Value1=Unknown, Value2=50V, ValueDisplayed=680pF
C24 C25 C26 C27 C30: library part CMP-0860983-1, "CAP, CERM, 0.1 µF, 50 V,+/- 10%, X7R, 0402", Cap_Case=0402, Manufacturer="Passive Plus", TempCo=X7R, Tolerance_%=10%, Value2=50V, ValueDisplayed=0.1µF
C34 C35 C36: library part CMP-0006723-4, "CAP, CERM, 1000 pF, 100 V, +/- 5%, X7R, 0603", Cap_Case=0603, Manufacturer=AVX, Supplier Part Number 1=478-3698-1-ND, TempCo=X7R, Tolerance_%=5%, Value1="0.276 ohm", Value2=100V, ValueDisplayed=1000pF
C37: library part CMP-0007185-4, "CAP, CERM, 150 pF, 50 V, +/- 5%, C0G/NP0, 0603", Cap_Case=0603, Manufacturer=MuRata, Supplier Part Number 1=490-1431-1-ND, TempCo=C0G/NP0, Tolerance_%=5%, Value1=Unknown, Value2=50V, ValueDisplayed=150pF
C38 C39 C40 C41: library part CMP-0007468-5, "CAP, CERM, 0.01 uF, 100 V, +/- 10%, X7R, 0603", Cap_Case=0603, Manufacturer=MuRata, Supplier Part Number 1=GRM188R72A103KA01D-ND, TempCo=X7R, Tolerance_%=10%, Value1=Unknown, Value2=100V, ValueDisplayed=0.01uF
C42: library part CMP-0006889-4, "CAP, CERM, 0.018 uF, 100 V, +/- 10%, X7R, 0603", Cap_Case=0603, Manufacturer=Kemet, Supplier Part Number 1=399-3475-1-ND, TempCo=X7R, Tolerance_%=10%, Value1=Unknown, Value2=100V, ValueDisplayed=0.018uF
D1 D2: library part CMP-0028433-2, "Diode, Schottky, 60 V, 5 A, SMC", Manufacturer="Diodes Inc.", Value1=5A, Value2=0.7V
D3 D4: library part CMP-0077011-2, "Diode, Schottky, 60 V, 1 A, SOD-323F", Manufacturer=Nexperia, Value1=1A, Value2=0.66V
FID1 FID2 FID3 FID4 FID5 FID6: library part CMP-0077181-1, "Fiducial mark.  There is nothing to buy or mount.", Manufacturer=N/A
H1 H2 H3 H4: library part CMP-0003617-1, "Machine Screw, Round, #4-40 x 1/4, Nylon, Philips panhead", Manufacturer="B&F Fastener Supply", Supplier Part Number 1=H542-ND
H5 H6 H7 H8: library part CMP-0003610-1, "Standoff, Hex, 0.5\"L #4-40 Nylon", Manufacturer=Keystone, Supplier Part Number 1=36-1902C-ND
J1 J2 J3 J4: library part CMP-0055387-2, "Standard Banana Jack, Uninsulated, 15A", Manufacturer="Cinch Connectivity", Supplier Part Number 1=J147-ND
J5 J6: library part CMP-0054801-2, "Header, 2.54 mm, 6x1, Gold, TH", Color=Black, Manufacturer="Wurth Elektronik", Supplier Part Number 1=732-5319-ND
J7 J8 J9 J10: library part CMP-0054794-2, "Header, 2.54 mm, 2x1, Gold, TH", Color=Black, Manufacturer="Wurth Elektronik", Supplier Part Number 1=732-5315-ND
J11 JP1 JP2 JP3 JP5: library part CMP-0054796-4, "Header, 2.54 mm, 3x1, Gold, TH", Manufacturer="Wurth Elektronik", Supplier Part Number 1=732-5316-ND
J12: library part CMP-0055448-2, "Header (shrouded), 100mil, 5x2, High-Temperature, Gold, TH", Manufacturer=3M, Supplier Part Number 1=MHC10K-ND
JP4: library part CMP-0055587-2, "Header, 2.54mm, 3x2, Gold, TH", Color=Natural, Manufacturer=Samtec, Supplier Part Number 1=HTSW-103-07-G-D-ND
JP6: library part CMP-0084909-1, "Header, 2.54mm, 5x1, Gold, TH", Color=Black, Current_A=3A, Manufacturer="Wurth Elektronik", Voltage_V=250V
L1: library part CMP-0063502-1, "Inductor, Shielded, Powdered Iron, 1.8 uH, 24 A, 0.0032 ohm, SMD", Manufacturer=Vishay-Dale, Supplier Part Number 1=IHLP5050FDER1R8M01-ND, Value1="0.0032 ohm", Value2=24A, ValueDisplayed=1.8uH
Logo5: library part CMP-0074837-2, "IEC 61010-1 Hot Surface Warning", Manufacturer="Texas Instruments"
NT1 NT2: library part CMP-0078142-6, "Single point connection between nets.", Manufacturer=N/A
Q1 Q2 Q3 Q4: library part CMP-0000747-1, "MOSFET, N-CH, 40 V, 75 A, PowerPAK_SO-8L", Alternate Manufacturer=None, Manufacturer=Vishay-Siliconix, Supplier Part Number 1=SQJ422EP-T1-GE3-ND, Value1=0.004, Value2="67 nC"
Q5: library part CMP-0000367-2, "Transistor, PNP, 45 V, 0.5 A, AEC-Q101, SOT-23", Manufacturer="ON Semiconductor", Supplier Part Number 1=BC807-40LT1GOSCT-ND, Value1="0.5 A", Value2=600
R1: library part CMP-0023259-5, "RES, 71.5 k, 1%, 0.1 W, 0603", Manufacturer=Yageo, Power_W=100mW, Supplier Part Number 1=311-71.5KHRCT-ND, TempCo="100 ppm/C", Tolerance_%=1%, Value2=0.1W, Value_Code=71k5, ValueDisplayed=71.5k
R2 R54: library part CMP-0023153-5, "RES, 4.70 k, 1%, 0.1 W, 0603", Manufacturer=Yageo, Power_W=100mW, Supplier Part Number 1=311-4.70KHRCT-ND, TempCo="100 ppm/C", Tolerance_%=1%, Value2=0.1W, Value_Code=4k70, ValueDisplayed=4.70k
R3 R4 R5 R6: library part CMP-0090660-1, "4 mOhms ±1% 1W Chip Resistor Wide 0805 (2012 Metric), 0508 Automotive AEC-Q200, Current Sense Metal Foil", Digikey Part Number=408-1594-1-ND, Manufacturer=Susumu, Mouser Part Number=754-KRL2012EMR004FT5, Operating Temperature Range="-55°C to +155°C", Power_W=1W, TempCo=50ppm/°C, Tolerance_%=1%
R7 R8 R9 R10 R13 R39: library part CMP-0025804-4, "RES, 3.0, 5%, 0.1 W, AEC-Q200 Grade 0, 0603", Manufacturer=Vishay-Dale, Power_W=100mW, Supplier Part Number 1=541-3.0GCT-ND, TempCo="200 ppm/C", Tolerance_%=5%, Value2=0.1W, Value_Code=3R00, ValueDisplayed=3.0
R11 R12: library part CMP-0084243-1, "RES, 100, 1%, 0.25 W, AEC-Q200 Grade 0, 0603", Manufacturer=Vishay-Dale, Power_W=250mW, TempCo="100 ppm/C", Tolerance_%=1%, Value2=0.25W, Value_Code=100R, ValueDisplayed=100
R14: library part CMP-0023267-5, "RES, 75.0 k, 1%, 0.1 W, 0603", Manufacturer=Yageo, Power_W=100mW, Supplier Part Number 1=311-75.0KHRCT-ND, TempCo="100 ppm/C", Tolerance_%=1%, Value2=0.1W, Value_Code=75k0, ValueDisplayed=75.0k
R15: library part CMP-0023073-5, "RES, 39.0 k, 1%, 0.1 W, 0603", Manufacturer=Yageo, Power_W=100mW, Supplier Part Number 1=311-39.0KHRCT-ND, TempCo="100 ppm/C", Tolerance_%=1%, Value2=0.1W, Value_Code=39k0, ValueDisplayed=39.0k
R16: library part CMP-0023653-3, "RES, 10.0 k, 0.1%, 0.1 W, 0603", Manufacturer="Yageo America", Power_W=100mW, TempCo="25 ppm/C", Tolerance_%=0.1%, Value2=0.1W, Value_Code=10k0, ValueDisplayed=10.0k
R17: library part CMP-0023292-5, "RES, 82.0 k, 1%, 0.1 W, 0603", Manufacturer=Yageo, Power_W=100mW, Supplier Part Number 1=311-82.0KHRCT-ND, TempCo="100 ppm/C", Tolerance_%=1%, Value2=0.1W, Value_Code=82k0, ValueDisplayed=82.0k
R18 R40 R41 R42 R43 R44 R46 R47 R48 R49 R50 R51 R52: library part CMP-0023343-3, "RES, 0, 1%, 0.1 W, AEC-Q200 Grade 0, 0603", Manufacturer="Stackpole Electronics Inc", Power_W=100mW, Supplier Part Number 1=RMCF0603ZT0R00CT-ND, TempCo=ppm/C, Tolerance_%=1%, Value2=0.1W, Value_Code=0
R19 R22 R23: library part CMP-0023000-5, "RES, 2.00 k, 1%, 0.1 W, 0603", Manufacturer=Yageo, Power_W=100mW, Supplier Part Number 1=311-2.00KHRCT-ND, TempCo="100 ppm/C", Tolerance_%=1%, Value2=0.1W, Value_Code=2k00, ValueDisplayed=2.00k
R20: library part CMP-0022552-4, "RES, 68.1 k, 1%, 0.1 W, AEC-Q200 Grade 0, 0603", Manufacturer=Vishay-Dale, Power_W=100mW, Supplier Part Number 1=541-68.1KHCT-ND, TempCo="100 ppm/C", Tolerance_%=1%, Value2=0.1W, Value_Code=68k1, ValueDisplayed=68.1k
R21: library part CMP-0023275-5, "RES, 78.7 k, 1%, 0.1 W, 0603", Manufacturer=Yageo, Power_W=100mW, Supplier Part Number 1=311-78.7KHRCT-ND, TempCo="100 ppm/C", Tolerance_%=1%, Value2=0.1W, Value_Code=78k7, ValueDisplayed=78.7k
R24: library part CMP-0022481-5, "RES, 511, 1%, 0.1 W, AEC-Q200 Grade 0, 0603", Manufacturer=Vishay-Dale, Power_W=100mW, Supplier Part Number 1=541-511HCT-ND, TempCo="100 ppm/C", Tolerance_%=1%, Value2=0.1W, Value_Code=511R, ValueDisplayed=511
R25: library part CMP-0022115-4, "RES, 1.15 k, 1%, 0.1 W, AEC-Q200 Grade 0, 0603", Manufacturer=Vishay-Dale, Power_W=100mW, Supplier Part Number 1=541-1.15KHCT-ND, TempCo="100 ppm/C", Tolerance_%=1%, Value2=0.1W, Value_Code=1k15, ValueDisplayed=1.15k
R26: library part CMP-0022891-5, "RES, 1.87 k, 1%, 0.1 W, 0603", Manufacturer=Yageo, Power_W=100mW, Supplier Part Number 1=311-1.87KHRCT-ND, TempCo="100 ppm/C", Tolerance_%=1%, Value2=0.1W, Value_Code=1k87, ValueDisplayed=1.87k
R27: library part CMP-0022996-5, "RES, 2.70 k, 1%, 0.1 W, 0603", Manufacturer=Yageo, Power_W=100mW, Supplier Part Number 1=311-2.70KHRCT-ND, TempCo="100 ppm/C", Tolerance_%=1%, Value2=0.1W, Value_Code=2k70, ValueDisplayed=2.70k
R28: library part CMP-0022381-4, "RES, 3.83 k, 1%, 0.1 W, AEC-Q200 Grade 0, 0603", Manufacturer=Vishay-Dale, Power_W=100mW, Supplier Part Number 1=541-3.83KHCT-ND, TempCo="100 ppm/C", Tolerance_%=1%, Value2=0.1W, Value_Code=3k83, ValueDisplayed=3.83k
R29: library part CMP-0023198-5, "RES, 5.10 k, 1%, 0.1 W, 0603", Manufacturer=Yageo, Power_W=100mW, Supplier Part Number 1=311-5.10KHRCT-ND, TempCo="100 ppm/C", Tolerance_%=1%, Value2=0.1W, Value_Code=5k10, ValueDisplayed=5.10k
R30: library part CMP-0023250-5, "RES, 6.49 k, 1%, 0.1 W, 0603", Manufacturer=Yageo, Power_W=100mW, Supplier Part Number 1=311-6.49KHRCT-ND, TempCo="100 ppm/C", Tolerance_%=1%, Value2=0.1W, Value_Code=6k49, ValueDisplayed=6.49k
R31: library part CMP-0023307-5, "RES, 8.25 k, 1%, 0.1 W, 0603", Manufacturer=Yageo, Power_W=100mW, Supplier Part Number 1=311-8.25KHRCT-ND, TempCo="100 ppm/C", Tolerance_%=1%, Value2=0.1W, Value_Code=8k25, ValueDisplayed=8.25k
R32: library part CMP-0022000-4, "RES, 10.5 k, 1%, 0.1 W, AEC-Q200 Grade 0, 0603", Manufacturer=Vishay-Dale, Power_W=100mW, Supplier Part Number 1=541-10.5KHCT-ND, TempCo="100 ppm/C", Tolerance_%=1%, Value2=0.1W, Value_Code=10k5, ValueDisplayed=10.5k
R33: library part CMP-0022790-5, "RES, 13.3 k, 1%, 0.1 W, 0603", Manufacturer=Yageo, Power_W=100mW, Supplier Part Number 1=311-13.3KHRCT-ND, TempCo="100 ppm/C", Tolerance_%=1%, Value2=0.1W, Value_Code=13k3, ValueDisplayed=13.3k
R34: library part CMP-0022079-4, "RES, 16.2 k, 1%, 0.1 W, AEC-Q200 Grade 0, 0603", Manufacturer=Vishay-Dale, Power_W=100mW, Supplier Part Number 1=541-16.2KHCT-ND, TempCo="100 ppm/C", Tolerance_%=1%, Value2=0.1W, Value_Code=16k2, ValueDisplayed=16.2k
R35: library part CMP-0022905-5, "RES, 20.5 k, 1%, 0.1 W, 0603", Manufacturer=Yageo, Power_W=100mW, Supplier Part Number 1=311-20.5KHRCT-ND, TempCo="100 ppm/C", Tolerance_%=1%, Value2=0.1W, Value_Code=20k5, ValueDisplayed=20.5k
R36: library part CMP-0022237-4, "RES, 24.9 k, 1%, 0.1 W, AEC-Q200 Grade 0, 0603", Manufacturer=Vishay-Dale, Power_W=100mW, Supplier Part Number 1=541-24.9KHCT-ND, TempCo="100 ppm/C", Tolerance_%=1%, Value2=0.1W, Value_Code=24k9, ValueDisplayed=24.9k
R37: library part CMP-0022324-4, "RES, 30.1 k, 1%, 0.1 W, AEC-Q200 Grade 0, 0603", Manufacturer=Vishay-Dale, Power_W=100mW, Supplier Part Number 1=541-30.1KHCT-ND, TempCo="100 ppm/C", Tolerance_%=1%, Value2=0.1W, Value_Code=30k1, ValueDisplayed=30.1k
R38: library part CMP-0022352-4, "RES, 35.7 k, 1%, 0.1 W, AEC-Q200 Grade 0, 0603", Manufacturer=Vishay-Dale, Power_W=100mW, Supplier Part Number 1=541-35.7KHCT-ND, TempCo="100 ppm/C", Tolerance_%=1%, Value2=0.1W, Value_Code=35k7, ValueDisplayed=35.7k
R45 R56 R58: library part CMP-0022751-4, "RES, 10.0, 1%, 0.1 W, 0603", Manufacturer=Yageo, Power_W=100mW, Supplier Part Number 1=311-10.0HRCT-ND, TempCo="100 ppm/C", Tolerance_%=1%, Value2=0.1W, Value_Code=10R0, ValueDisplayed=10.0
R53: library part CMP-0022735-5, "RES, 100 k, 1%, 0.1 W, 0603", Manufacturer=Yageo, Power_W=100mW, Supplier Part Number 1=311-100KHRCT-ND, TempCo="100 ppm/C", Tolerance_%=1%, Value2=0.1W, Value_Code=100k
R55 R57: library part CMP-0021998-4, "RES, 10.0 k, 1%, 0.1 W, AEC-Q200 Grade 0, 0603", Manufacturer=Vishay-Dale, Power_W=100mW, Supplier Part Number 1=541-10.0KHCT-ND, TempCo="100 ppm/C", Tolerance_%=1%, Value2=0.1W, Value_Code=10k0, ValueDisplayed=10.0k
